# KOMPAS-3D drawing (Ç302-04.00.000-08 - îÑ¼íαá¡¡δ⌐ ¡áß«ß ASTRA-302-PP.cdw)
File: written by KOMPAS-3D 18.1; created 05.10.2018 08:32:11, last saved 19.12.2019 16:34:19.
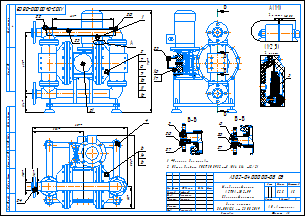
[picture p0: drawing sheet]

Sheet 1: A3, landscape

Document properties: Автор: Милов; Полное имя файла: D:\Мембранные насосы\Мембранный электропривод\А302-00.00.000 - ASTRA-302 (МЭ200)\А302-04.00.000 - Мембранный насос ASTRA-302-PP\А302-04.00.000-08 - Мембранный насос ASTRA-302-PP.cdw; Масса: 52.5

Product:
- Part/product: (unnamed)
  - Component: Фланец с буртом -50  | designation МФ-01.00.000-01  | pos. 0  | Раздел спецификации: Детали; Примечание: Заим.
  - Component: Труба @2~50 полипроипилен  | pos. 0  | Раздел спецификации: Детали; Примечание: 87 мм

Title block, sheet 1: Наименование: Мембранный насос / ASTRA-302-PP / Сборочный чертеж; designation: А302-04.00.000 - 08   СБ; Материал: Заказ клиента / ЭЛ-001126 от 23.08.2019; Масса: 52,5; scale: 1:5; Количество листов документа: 1; organisation: АО «Астерион»; Форматы листов документа: A3; stored path: \\192.168.87.28\Konstructor_doc\Мембранные насосы\Мембранный электропривод\А302-00.00.000 - ASTRA-302 (МЭ200)\3Д ПВХ\А302-01.00.000 - Мембранный насос ASTRA-302-PVC.cdw; Разработал: Лифлянд; Проверил: Борисенко; Т. контр.: Лучихин; Утвердил: Григорьева

Views: Выносной элемент А, Выносной элемент, Разрез Б-Б, Разрез В-В, Вид:1
Referenced files in D:\3Д модели\Крепеж\: Гайка шестигранная самостопорящаяся с фланцем DIN 6927-M6 - A2-70.m3d
Referenced files in D:\Мембранные насосы\Мембранный электропривод\А302-00.00.000 - ASTRA-302 (МЭ200)\3Д ПВХ\Отработка\: Отвод ПВХ 90гр 50 арт.GIV050.m3d, Труба ПВХ PN10 50х2,4.m3d, Тройник равносторонний ПВХ 90гр 50 арт.TIV050.m3d, Штуцер для шланга 50х52х50 арт.AIV050052050.m3d, Квадратная внутренняя заглушка 140х140 мм.m3d, А302-01.20.000 - Мотор-редуктор.a3d, А302-01.05.002 - Ловитель.m3d, Труба профильная 25х25х1,5.m3d, Труба профильная 25х25х1,5-1.m3d
Referenced files in D:\Мембранные насосы\Мембранный электропривод\А302-00.00.000 - ASTRA-302 (МЭ200)\3Д ПВХ\: А302-01.15.000 - Мембрана.a3d, А302-01.10.000 - Рабочая камера.a3d, А302-01.10.000 - Рабочая камера.cdw, А302-01.05.000 - Корпус.a3d, А302-01.40.000 - Каркас.a3d, А302-01.40.000 - Каркас.cdw, Виброопора PCA-60 M10.m3d, А302-01.20.001 - Основание.m3d, А302-01.35.000 - Фланец.a3d, А302-04.35.003 - Опора подшиника.m3d, А302-04.35.004 - Стенка.m3d, А302-01.20.002 - Эксцентрик.m3d, FB 063 .m3d, А302-01.15.001 - Мембрана.m3d, А302-01.15.003 - Шайба.m3d, А302-01.15.008 - Кольцо плоское Ф4.m3d, А302-01.15.001-01- Мембрана.m3d, А302-01.15.007 - Заглушка.m3d, А302-01.15.002 - Упор.a3d, А302-01.12.000 - Крышка.a3d, А302-01.12.001 - Крышка.m3d, Втулка резьбовая М6 (шт.) Alutech.m3d, А302-01.31.000 - Корпус со встроенными стаканами.m3d, А302-01.11.000 - Крышка рабочей камеры.a3d, А302-01.10.001 - Седло.m3d, А302-01.10.002 3Д - Стакан.m3d, А302-01.30.001 - Прижим.m3d, А302-01.30.000 - Прижим.a3d, А302-02.40.002 - Подставка 1.m3d, А302-02.40.003 - Подставка 2.m3d, А302-04.20.003 - Ползун из стержня.m3d, МФ-01.00.000-02 - Фланец с буртом -63.a3d, А302-01.00.000  - Мембранный насос ASTRA-302 ПВХ.a3d, А302-01.15.002 - Упор.m3d, А302-01.15.009 - Кольцо плоское Ф4.m3d, А302-01.15.011 - Заглушка резьбовая.m3d
Referenced files in \\192.168.87.28\Konstructor_doc\Мембранные насосы\Мембранный электропривод\А302-00.00.000 - ASTRA-302 (МЭ200)\3Д ПВХ\: А302-01.15.000 - Мембрана.cdw, А302-01.10.000 - Рабочая камера.cdw, А302-01.05.000 - Корпус.cdw, А302-01.40.000 - Каркас.cdw
Referenced files in D:\Мембранные насосы\Мембранный электропривод\А302-00.00.000 - ASTRA-302 (МЭ200)\А302-04.00.000 - Мембранный насос ASTRA-302-PP\: А302-02.40.000 - Каркас.cdw, А302-02.10.000 - Рабочая камера.cdw, А302-02.15.000 - Мембрана.cdw, А302-04.15.008 - Редукция на выход.m3d, А302-04.15.009 - Редукция на вход.m3d
Referenced files in D:\1 ПКИ 3D\Двигатели\АИР\: Электродвигатель АИР 80А4 IM 3081 1,1кВт 1400 об..m3d
Referenced files in D:\1 ПКИ 3D\Редуктора NMRW\Редукторы\: Редуктор NMRW 063.m3d, Червячный мотор-редуктор NMRV063 АИР80.a3d
Referenced files in D:\Мембранные насосы\Мембранный электропривод\А302-00.00.000 - ASTRA-302 (МЭ200)\3Д\: А302-00.35.002 - Пластина.m3d, А302-00.35.001 - Труба 140х140х4.m3d, А302-00.20.004 - Вал.m3d, А302-00.20.003 - Ползун.m3d, А302-00.05.001 - Основание.m3d
Referenced files in C:\Program Files\ASCON\KOMPAS-3D v18\Libs\PartLib\DATA\VAULT\methods\kompas\3d\: PLib_Check_spring_rings_GOST_13942_911.m3d, PLib_Washer_1_712.m3d, PLib_Bolt_1_900.m3d, PLib_Washer_2_712.m3d, PLib_Nut_OST92_900.m3d, PLib_Screw_DIN_7984_1500.m3d, PLib_Key_prismatic_712.m3d, PLib_Screw_ISO_10642_1500.m3d, PLib_Bolt_1_ISO_1100.m3d, PLib_Nut_ISO_1100.m3d
Referenced files in D:\1 ПКИ 3D\1 Крепеж стандартный\Подшипник\: Подшипник 52х25х15 62052RSH SKF.m3d, Подшипник 80х40х18 6208-2RS1 SKF.m3d
Referenced files in D:\2 Стандартные изделия 3D\Гайки\DIN 6927\: Гайка шестигранная самостопорящаяся с фланцем DIN 6927-M5 - A2-70.m3d, Гайка шестигранная самостопорящаяся с фланцем DIN 6927-M6 - A2-70.m3d
Referenced files in D:\1 ПКИ 3D\ПВХ фитинги, трубы\: Труба PVC-U 50 3,7.m3d
Referenced files in D:\2 Стандартные изделия 3D\Винты\Din 912\: Винт DIN 912-М6х100-А2-70.m3d
Referenced files in D:\1 ПКИ 3D\2 Китай\: Шар PTFE ф60.m3d
Referenced files: Заготовка стакан.m3d
Referenced files in D:\1 ПКИ 3D\Полипропиленовые фитинги, трубы\Трубы\: Труба 50 PN10 S=4,6 FV PPR ф. FV PLAST.m3d
Referenced files in D:\1 ПКИ 3D\РТИ\Кольца ГОСТ 9833-76\: Кольцо 072-78-25 EPDM ГОСТ 9833-76.m3d
Referenced files in D:\1 ПКИ 3D\Полипропиленовые фитинги, трубы\: Колено 90 ф50 ф.FV Plast.m3d, Тройник 50 FV PPR ф. FV PLAST.m3d, Труба ф50х4,6 FV PPR  (PN 10)  ф. FV PLAST.m3d, FV PPR Фальцевый бурт 50.m3d, FV PPR FE Свободный фланец к фальцевому бурту.m3d, FV PPR Патрубок 50 арт. AA201050000.m3d
Referenced files in D:\1 ПКИ 3D\Крышечки NMRW (габаритные модели)\: МИКС К 00.00.001-04 - Крышка.m3d
Referenced files in C:\Program Files\ASCON\KOMPAS-3D v18\Libs\PARTLib\DATA\vault\Methods\Kompas\3D\: PLib_Screw_GOST_11738_1500.m3d
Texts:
  Шайба 6 30Х13 019 ГОСТ 6402-70
  Шайба
  ГОСТ
  Шайба C.6.21 ГОСТ 11371-78
  Гайка шестигранная самостопорящаяся
  с фланцем DIN 6927-M6-A2-70
  Гайка
  шестигранная
  самостопорящаяся
  фланцем
  DIN
  Отвод ПВХ 90   50 арт.GIV050
  Отвод ПВХ 90@1~ @2~50 арт.GIV050
  Винт с цилиндрической головкой
  и шестигранным углублением под ключ
  ГОСТ Р ИСО  4762-М8 x 40-6.8-A9J
  Винт
  цилиндрической
  головкой
  шестигранным
  углублением
  под
  ключ
  ИСО
  Нерж.
  ГОСТ Р ИСО  4762-М6 x 50-A2-70
  Винт с цилиндрической головкой и шестигранным углублением под ключ ГОСТ Р ИСО  4762-М6 x 50-A2-70
  Труба ПВХ PN10 50х2,4
  Шайба C.8.04.019 ГОСТ 11371-78
  Гайка М8-6H.5.019 ГОСТ 5915-70
  Шайба 8 30Х13 019 ГОСТ 6402-70
  Мембрана
  Рабочая камера
  Шайба C 12.21 ГОСТ 6958-78
  Корпус
  @100~)2xA3
  Тройник равносторонний
  ПВХ 90   50 арт.TIV050
  Тройник равносторонний / ПВХ 90@1~ @2~50 арт.TIV050
  Винт с потайной головкой и
  шестигранным углублением под ключ
  ГОСТ Р ИСО  10642-М8 x 40-8.8-A3J
  потайной
  Штуцер ПВХ для шланга 50х52х50
  арт.AIV050052050
  Штуцер ПВХ для шланга 50х52х50 / арт.AIV050052050
  Квадратная внутренняя заглушка 140х140 мм
  Каркас
  Виброопора PCA-60 M10
  МФ-01.00.000 - 01
  МФ-01.00.000 - 01
  Фланец с буртом -50
  Заим.
  Труба  50 полипроипилен
  Труба @2~50 полипроипилен
  Электродвигатель / АИР 80А4 IM 3081 1,1кВт 1400 об/мин
  Редуктор NMRW 063
  Мотор-редуктор / NMRV063 N P(кВт) V5 / P(мощн./дв.), i(передат. отн.) см. заказ
  Основание
  Пластина
  Труба 140х140х6
  Опора подшипника
  Стенка
  Фланец
  Эксцентрик
  Кольцо A25.65Г ГОСТ 13942-86
  Подшипник 52х25х15 62052RSH SKF
  Вал
  Ползун
  Болт М6-6gx40 ГОСТ 7805-70
  Гайка М6-6H.21.12Х18Н10Т ГОСТ 5915-70
  Шайба C.8.21 ГОСТ 11371-78
  Винт с цилиндрической головкой и шестигранным углублением под ключ ГОСТ Р ИСО 4762 - М8 x 25 - A2-70
  Гайка М8-6H.21.12Х18Н10Т ГОСТ 5915-70
  Шпонка 8x7x90 ГОСТ 23360-78
  FB 063
  Винт с цилиндрической головкой и шестигранным углублением под ключ ГОСТ Р ИСО 4762-М8 x 25-A2-70
  Подшипник 80х40х18 6208-2RS1 SKF
  Кольцо A40.65Г ГОСТ 13942-86
  Мотор-редуктор
  Ловитель
  Шайба C 8.04.019 ГОСТ 6958-78
  Болт М8-6gx35.58.019 ГОСТ 7805-70
  Винт с потайной головкой и шестигранным углублением под ключГОСТ Р ИСО 10642-М4x20-8.8-A3J
  Шайба (нарощеннАЯ)
  Упор
  Болт с шестигранной головкой с фланцем ГОСТ Р 55739-М5 x 25-A2-70
  Гайка шестигранная с фланцем ГОСТ Р ИСО 4161 - M5 - A2-70
  Гайка шестигранная самостопорящаяся с фланцем / DIN 6927-M5-A2-70
  Кольцо плоское  / уплотнительное 5-13-10 Ф4
  Кольцо плоское Ф4
  Заглушка
  Заглушка резьбовая
  Болт с шестигранной головкой с фланцем ГОСТ Р 55739-М8 x 16-A2-70
  Крышка
  ART. 9058 ВТУЛКА РЕЗЬБОВАЯ С ВНЕШН. И ВНУТР. РЕЗЬБОЙ M6 / M10 X 14 ММ А1-НЕРЖ
  Труба полипропиленовая 50*4,6
  Отвод ПВХ 45@1~ @2~50 арт.HIV050
  Корпус со встроенными стаканами
  Шайба 6 30Х13 ГОСТ 6402-70
  Винт с цилиндрической головкой / и вн. шестигранником / DIN 912-М6х80-А2-70
  Крышка рабочей камеры
  Седло
  Шар @2~60mm PTFE / для мембранного насоса
  Стакан
  Прижим
  Труба 50 PN10 S=4,6 FV PPR ф. FV PLAST
  Гайка шестигранная самостопорящаяся с фланцем / DIN 6927-M6 - A2-70
  Винт с цилиндрической головкой и шестигранным углублением под ключ ГОСТ Р ИСО  4762-М6 x 40-A2-70
  Кольцо 072-078-25 / материал EPDM ГОСТ 9833-76
  Штифт 10х40
  Винт с цилиндрической головкой и шестигранным углублением под ключГОСТ Р ИСО 4762-М6x50-A2-70
  Гайка шестигранная самостопорящаяся / с фланцем DIN 6927-M6-A2-70
  Труба профильная 20х20х1,5 / Ст3 ГОСТ 380-2005
  Опора
  Подставка 1
  Подставка 2
  Винт с потайной головкой и шестигранным углублением под ключГОСТ Р ИСО 10642-М8x40-8.8-A3J
  Винт с цилиндрической головкой и шестигранным углублением под ключГОСТ Р ИСО 4762-М8x40-6.8-A9J
  Штуцер PP-H для шланга 50х90х50 / арт.Georg Fischer 727 960 410
  Колено 90 @2~50 ф.FV Plast
  Тройник @2~50 FV PPR ф. "FV PLAST"
  Труба 50 PN10 S=4,6 FV PPR ф. "FV PLAST"
  МИКС К 00.00.001-04
  Шайба C.8.37 ГОСТ 11371-78
  Винт М8-6gx20 ГОСТ 11738-84
  Ползун из стержня
  Уголок $d В-63 х 40 х 4 ГОСТ 8510-86 ; Ст2сп ГОСТ 535-88$
  Бурт-50
  МБ-00.00.001
  Фланец-50
  МФ-00.00.002
  МФ-01.00.000
  Заглушка пластиковая круглая 130 Артикул: ILT130
  Редукция на выход
  Редукция на вход
  Мембранный насос ASTRA-302-PP
Dimensions and other numbers on the sheet: 4; 10; 0; 1; 13; 5; 16; 7; 6; 18; 50; 14; 9; 11; 3; 2; 12; 17; 8; 19; 15; 20; 71; 87 мм; 1:5; 52,5; 777; 07; 01; 02; 08

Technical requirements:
  *Размеры для справок.
  Общие допуски ГОСТ 30893.2-mK (H14, h14,  t2/2).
